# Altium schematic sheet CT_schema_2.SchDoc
size 362 x 325 mm
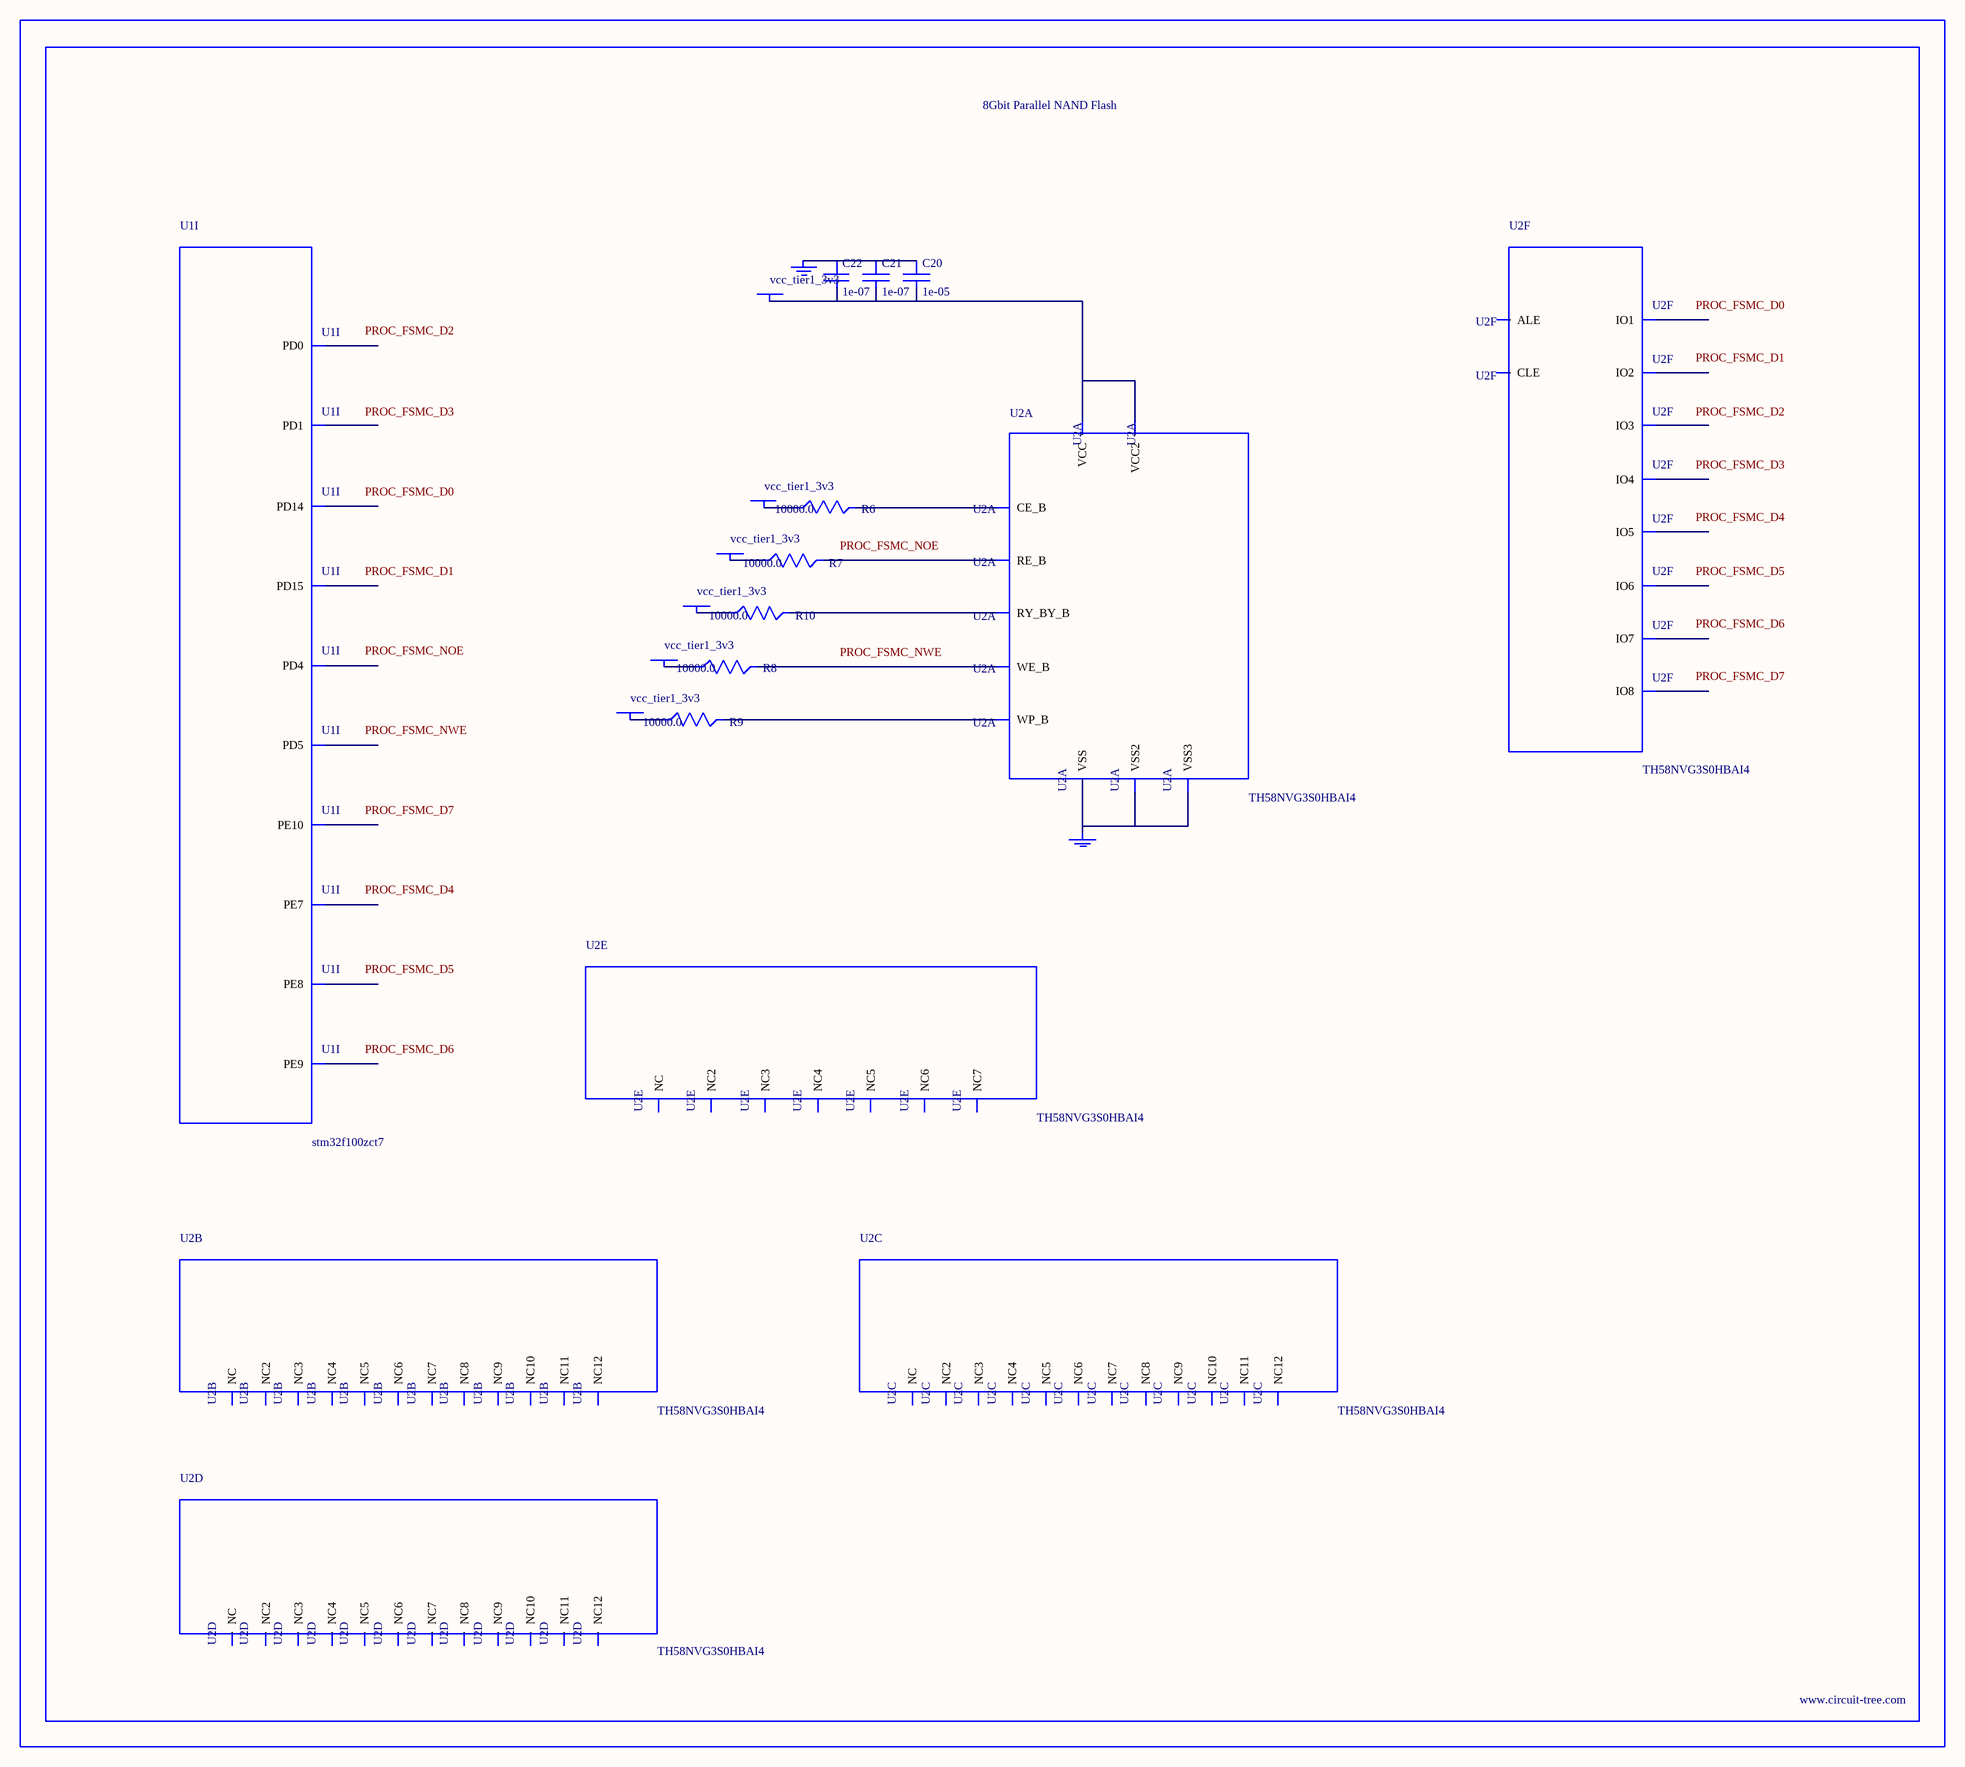
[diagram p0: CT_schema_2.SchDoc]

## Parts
BORDER1  (no value)
C20  1e-05  [C0805]
C21  1e-07  [C0402]
C22  1e-07  [C0402]
GND_INSTANCE_1_0  (no value)
GND_INSTANCE_1_1  (no value)
POWER_INSTANCE_1_0  vcc_tier1_3v3
POWER_INSTANCE_1_1  vcc_tier1_3v3
POWER_INSTANCE_1_2  vcc_tier1_3v3
POWER_INSTANCE_1_3  vcc_tier1_3v3
POWER_INSTANCE_1_4  vcc_tier1_3v3
POWER_INSTANCE_1_5  vcc_tier1_3v3
R6  10000.0  [R0603]
R7  10000.0  [R0603]
R8  10000.0  [R0603]
R9  10000.0  [R0603]
R10  10000.0  [R0603]
U1  stm32f100zct7  [LQFP144]  (part I of 10)
U2  TH58NVG3S0HBAI4  [TH58NVG3S0HBAI4]  (parts A,B,C,D,E,F of 6)

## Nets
NetC20_1: C20.1 C21.1 C22.1 GND_INSTANCE_1_0.0(GND)
NetC20_2: C20.2 C21.2 C22.2 POWER_INSTANCE_1_5.0(PWR) U2.H8(VCC) U2.J6(VCC2)
NetGND_INSTANCE_1_1_0: GND_INSTANCE_1_1.0(GND) U2.C5(VSS) U2.K3(VSS2) U2.K8(VSS3)
NetPOWER_INSTANCE_1_0_0: POWER_INSTANCE_1_0.0(PWR) R6.1
NetPOWER_INSTANCE_1_1_0: POWER_INSTANCE_1_1.0(PWR) R7.1
NetPOWER_INSTANCE_1_2_0: POWER_INSTANCE_1_2.0(PWR) R8.1
NetPOWER_INSTANCE_1_3_0: POWER_INSTANCE_1_3.0(PWR) R9.1
NetPOWER_INSTANCE_1_4_0: POWER_INSTANCE_1_4.0(PWR) R10.1
NetR6_2: R6.2 U2.C6(CE_B)
NetR7_2: R7.2 U2.D4(RE_B)
NetR8_2: R8.2 U2.C7(WE_B)
NetR9_2: R9.2 U2.C3(WP_B)
NetR10_2: R10.2 U2.C8(RY_BY_B)

Not connected (* = marked no-connect by the designer): U1 58(PE7) 59(PE8) 60(PE9) 63(PE10) 85(PD14) 86(PD15) 114(PD0) 115(PD1) 118(PD4) 119(PD5); U2 A1(NC) A2(NC3) A9(NC4) A10(NC2) B1(NC5) B9(NC7) B10(NC6) C4(ALE) D3(NC8) D5(CLE) D6(NC9) D7(NC10) D8(NC11) E3(NC12) E4(NC) E5(NC2) E6(NC3) E7(NC4) E8(NC5) F3(NC6) F4(NC7) F5(NC8) F6(NC9) F7(NC10) F8(NC11) G3(NC12) G4(NC) G5(NC2) G6(NC3) G7(NC4) G8(NC5) H3(NC6) H4(IO1) H5(NC7) H6(NC8) H7(NC9) J3(NC10) J4(IO2) J5(NC11) J7(IO6) J8(IO8) K4(IO3) K5(IO4) K6(IO5) K7(IO7) L1(NC12) L2(NC2) L9(NC3) L10(NC) M1(NC4) M2(NC6) M9(NC7) M10(NC5)

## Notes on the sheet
- Labels drawn without touching a wire or pin: PROC_FSMC_D0, PROC_FSMC_D1, PROC_FSMC_D2, PROC_FSMC_D3, PROC_FSMC_D4, PROC_FSMC_D5, PROC_FSMC_D6, PROC_FSMC_D7, PROC_FSMC_NOE, PROC_FSMC_NWE

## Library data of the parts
BORDER1 = BORDER_PAGE1
C20 = C0805C106K8RACTU
C21 C22 = C0402C104K3RACTU
GND_INSTANCE_1_0 GND_INSTANCE_1_1 = GND
POWER_INSTANCE_1_0-POWER_INSTANCE_1_5 = PWR
R6-R10 = RC0603JR-0710KL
